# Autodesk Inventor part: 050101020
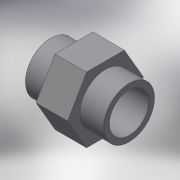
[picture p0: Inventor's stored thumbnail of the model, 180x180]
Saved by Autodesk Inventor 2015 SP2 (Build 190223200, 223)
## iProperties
Created: 2017-10
Part Number: 050101020
Material: Generic
Description: PLASSON THREADED SOCKET PVC 2"
Document SubType Name: Modeling
Designer: KIM
Density: 1 g/cm^3
Appearance: Default
Author: KIM
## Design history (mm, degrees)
derived "050101.ipt"
feature "Solid1::050101.ipt"
tag "TaggingFeature1"
body "Solid1"
other parameters: "d0" = 68, "d1" = 56.656, "d3" = 56.656, "d4" = 50.9904, "d5" = 26, "d6" = 26, "d7" = 73.6528, "d8" = 73.6528, "d10" = 18.2, "d13" = 0, "d14" = 0.56656, "d15" = 16, "G_" = 56.656, "B_" = 16, "lt_" = 26, "H_" = 68
